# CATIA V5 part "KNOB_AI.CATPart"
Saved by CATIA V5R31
Part number: KNOB_AI
Source: Unknown
Bounding box of the stored display mesh (mm): x -6.041 to 6.111, y -7.718 to 2.844, z 21.583 to 21.763
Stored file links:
  \\solize.local\damia\dept\DDE_Design\10_order\2305701_JAMA_変換検証STEP3_お手本モデル作成\work\03_東洋電装_スイッチ\10_CATIA_V5\KNOB_AI.CATPart
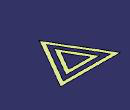
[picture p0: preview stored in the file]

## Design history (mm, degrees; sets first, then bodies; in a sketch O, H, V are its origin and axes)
WSupportSet1: ActiveGrid {3dwsupport RefPoint {point stored without definition}, 3DWOS ({wsupport Support xy-plane, RefPoint {3dwsupport}, GridIn {cartgrid Value 100, Stepbid1 0, Value 100, Stepbid2 0, Direction (1, 0, 0)}, GeometricData ({line type PtDir, Direction (1, 0, 0), Support xy-plane}; {line type PtDir, Direction (0, 1, 0), Support xy-plane})}; {wsupport Support yz-plane, RefPoint {3dwsupport}, GridIn {cartgrid Value 100, Stepbid1 0, Value 100, Stepbid2 0, Direction (0, 1, 0)}, GeometricData ({line type PtDir, Direction (0, 1, 0), Support yz-plane}; {line type PtDir, Direction (0, 0, 1), Support yz-plane})}; {wsupport Support zx-plane, RefPoint {3dwsupport}, GridIn {cartgrid Value 100, Stepbid1 0, Value 100, Stepbid2 0, Direction (0, 0, 1)}, GeometricData ({line type PtDir, Direction (0, 0, 1), Support zx-plane}; {line type PtDir, Direction (1, 0, 0), Support zx-plane})}), GeometricData ({line type PtDir, RefPoint {point stored without definition}, Direction (1, 0, 0), Support xy-plane}; {line type PtDir, RefPoint {point stored without definition}, Direction (0, 1, 0), Support xy-plane}; {line type PtDir, RefPoint {point stored without definition}, Direction (0, 1, 0), Support yz-plane}; {line type PtDir, RefPoint {point stored without definition}, Direction (0, 0, 1), Support yz-plane}; {line type PtDir, RefPoint {point stored without definition}, Direction (0, 0, 1), Support zx-plane}; {line type PtDir, RefPoint {point stored without definition}, Direction (1, 0, 0), Support zx-plane})}
Set1
  DatumSurface1 "Surface.10"
  DatumSurface2 "Surface.11"
Body1 (main body)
